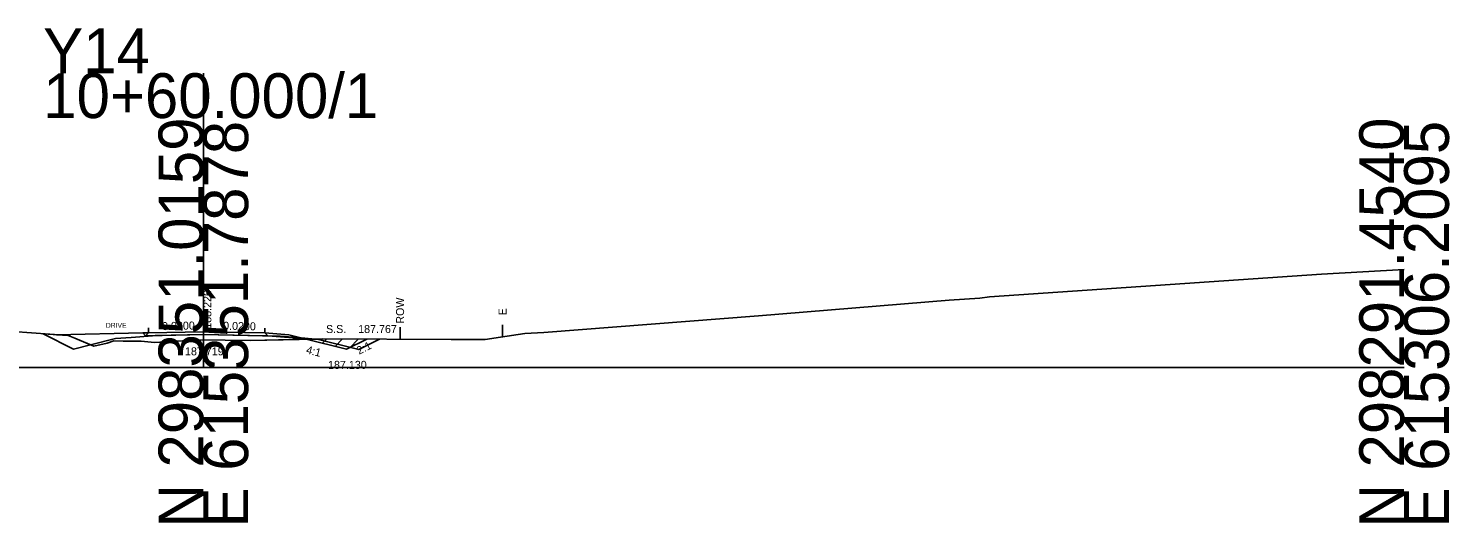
# Model space of a CAD drawing. Extents: x 517327 to 517505, y 114839 to 117370.
# Drawn here: x 517416.4 to 517505.2, y 116338.7 to 116369.5 of the extents above; entities that cross this region are included whole.
import ezdxf

# ---------------------------------------------------------------- set-up
doc = ezdxf.new("R2010")
doc.units = 0
for name, color, linetype in [('Exist XS Ground Line', 7, 'Continuous'), ('Old_Level_60', 7, 'Continuous'), ('Old_Level_63', 7, 'Continuous'), ('Prop XS Dump Level', 7, 'Continuous'), ('Prop XS Earthwork Shape', 7, 'Continuous'), ('Prop XS Elevation Labels', 7, 'Continuous'), ('Prop XS EOT Tick Mark', 7, 'Continuous'), ('Prop XS Exc Vertical Line 1', 7, 'Continuous'), ('Prop XS Exc Vertical Line 2', 7, 'Continuous'), ('Prop XS Finish Grade', 7, 'Continuous'), ('Prop XS Finish Grade Earthwork', 7, 'Continuous'), ('Prop XS Finish Grade Pavement', 7, 'Continuous'), ('Prop XS Hydro Elevations', 7, 'Continuous'), ('Prop XS Label Text', 7, 'Continuous'), ('Prop XS Pvmt Edge Slope', 7, 'Continuous'), ('Prop XS SE Text', 7, 'Continuous'), ('Prop XS Side Slope Text', 7, 'Continuous'), ('Prop XS Subgrade Earthwork', 7, 'Continuous'), ('Prop XS Suitable Common Exc Shape', 7, 'Continuous'), ('Scratch_Level_0', 7, 'Continuous')]:
    doc.layers.add(name, color=color, linetype=linetype)

msp = doc.modelspace()

# ---------------------------------------------------------------- linework, layer by layer
at = {"layer": 'Exist XS Ground Line'}
for p, q in [((517476.474, 116352.763), (517497.196, 116354.197)), ((517497.196, 116354.197), (517502.365, 116354.49)), ((517462.046, 116351.595), (517473.955, 116352.558)), ((517473.955, 116352.558), (517475.855, 116352.699)), ((517475.855, 116352.699), (517476.474, 116352.763)), ((517448.633, 116350.545), (517462.046, 116351.595)), ((517415.494, 116350.598), (517418.926, 116350.355)), ((517418.926, 116350.355), (517419.337, 116350.188)), ((517419.337, 116350.188), (517420.516, 116349.683)), ((517420.516, 116349.683), (517421.365, 116349.878)), ((517421.365, 116349.878), (517421.772, 116350.019)), ((517421.772, 116350.019), (517422.348, 116350.001)), ((517422.348, 116350.001), (517423.492, 116350.003)), ((517423.492, 116350.003), (517424.31, 116349.923)), ((517424.31, 116349.923), (517425.622, 116349.995)), ((517425.622, 116349.995), (517427.362, 116350.084)), ((517427.362, 116350.084), (517428.73, 116350.061)), ((517428.73, 116350.061), (517430.338, 116350.036)), ((517430.338, 116350.036), (517434.785, 116350.148)), ((517434.785, 116350.148), (517442.835, 116350.1)), ((517442.835, 116350.1), (517444.961, 116350.102)), ((517444.961, 116350.102), (517445.929, 116350.255)), ((517445.929, 116350.255), (517447.446, 116350.473)), ((517447.446, 116350.473), (517448.633, 116350.545))]:
    msp.add_line(p, q, dxfattribs=at)
at = {"layer": 'Old_Level_63'}
for p, q in [((517427.365, 116348.365), (517427.365, 116366.739)), ((517352.365, 116348.365), (517427.365, 116348.365)), ((517427.365, 116348.365), (517502.365, 116348.365))]:
    msp.add_line(p, q, dxfattribs=at)
at = {"layer": 'Prop XS Dump Level'}
for p, q in [((517423.941, 116350.523), (517427.365, 116350.591)), ((517427.365, 116350.591), (517431.204, 116350.514))]:
    msp.add_line(p, q, dxfattribs=at)
at = {"layer": 'Prop XS Earthwork Shape'}
for points in [[(517423.758, 116350.339), (517423.941, 116350.343), (517427.365, 116350.411), (517431.204, 116350.334), (517431.387, 116350.331), (517432.704, 116350.225), (517433.698, 116350.146), (517433.788, 116350.123), (517430.338, 116350.036), (517428.73, 116350.061), (517427.362, 116350.084), (517425.622, 116349.995), (517424.31, 116349.923), (517423.492, 116350.003), (517422.348, 116350.001), (517421.772, 116350.019), (517421.365, 116349.878), (517420.516, 116349.683), (517419.337, 116350.188), (517418.926, 116350.355), (517418.186, 116350.407), (517423.581, 116350.515)], [(517436.304, 116349.494), (517437.578, 116350.132), (517434.785, 116350.148), (517433.788, 116350.123)]]:
    msp.add_lwpolyline(points, close=True, dxfattribs=at)
at = {"layer": 'Prop XS EOT Tick Mark'}
for p, q in [((517423.941, 116350.827), (517423.941, 116350.523)), ((517431.204, 116350.514), (517431.204, 116350.819))]:
    msp.add_line(p, q, dxfattribs=at)
at = {"layer": 'Prop XS Exc Vertical Line 1'}
msp.add_line((517446.056, 116351.023), (517446.056, 116350.273), dxfattribs=at)
at = {"layer": 'Prop XS Exc Vertical Line 2'}
msp.add_line((517439.652, 116350.869), (517439.652, 116350.119), dxfattribs=at)
at = {"layer": 'Prop XS Finish Grade'}
for p, q in [((517423.581, 116350.515), (517423.941, 116350.523)), ((517431.204, 116350.514), (517432.704, 116350.394)), ((517432.704, 116350.394), (517433.698, 116350.146))]:
    msp.add_line(p, q, dxfattribs=at)
at = {"layer": 'Prop XS Finish Grade Earthwork'}
for p, q in [((517423.581, 116350.515), (517418.186, 116350.407)), ((517433.698, 116350.146), (517436.304, 116349.494)), ((517436.304, 116349.494), (517437.578, 116350.132))]:
    msp.add_line(p, q, dxfattribs=at)
at = {"layer": 'Prop XS Finish Grade Pavement'}
for p, q in [((517427.365, 116350.591), (517423.941, 116350.523)), ((517431.204, 116350.514), (517427.365, 116350.591))]:
    msp.add_line(p, q, dxfattribs=at)
at = {"layer": 'Prop XS Pvmt Edge Slope'}
for p, q in [((517423.758, 116350.339), (517423.941, 116350.523)), ((517431.204, 116350.514), (517431.387, 116350.331))]:
    msp.add_line(p, q, dxfattribs=at)
at = {"layer": 'Prop XS Subgrade Earthwork'}
for p, q in [((517423.758, 116350.339), (517423.581, 116350.515)), ((517423.758, 116350.339), (517423.941, 116350.343)), ((517427.365, 116350.411), (517423.941, 116350.343)), ((517431.204, 116350.334), (517427.365, 116350.411)), ((517431.204, 116350.334), (517431.387, 116350.331)), ((517431.387, 116350.331), (517432.704, 116350.225)), ((517432.704, 116350.225), (517433.698, 116350.146))]:
    msp.add_line(p, q, dxfattribs=at)
at = {"layer": 'Prop XS Suitable Common Exc Shape'}
for points in [[(517419.337, 116350.188), (517420.309, 116349.772), (517419.265, 116349.511), (517417.355, 116350.466), (517418.926, 116350.355)], [(517433.475, 116350.21), (517434.375, 116350.138), (517430.338, 116350.036), (517428.73, 116350.061), (517427.362, 116350.084), (517425.622, 116349.995), (517424.31, 116349.923), (517423.492, 116350.003), (517422.348, 116350.001), (517421.772, 116350.019), (517421.365, 116349.878), (517420.516, 116349.683), (517420.309, 116349.772), (517421.871, 116350.163), (517422.865, 116350.242), (517424.181, 116350.347), (517424.365, 116350.351), (517427.365, 116350.411), (517431.975, 116350.319), (517432.158, 116350.315)], [(517434.785, 116350.148), (517438.371, 116350.127), (517437.075, 116349.479), (517434.469, 116350.13), (517434.375, 116350.138)]]:
    msp.add_lwpolyline(points, close=True, dxfattribs=at)
at = {"layer": 'Scratch_Level_0'}
for p, q in [((517433.788, 116350.123), (517434.785, 116350.148)), ((517436.304, 116349.494), (517433.788, 116350.123)), ((517434.009, 116350.068), (517434.072, 116350.13)), ((517434.785, 116350.148), (517437.578, 116350.132)), ((517434.801, 116349.87), (517435.078, 116350.146)), ((517435.593, 116349.672), (517436.062, 116350.141)), ((517437.578, 116350.132), (517436.304, 116349.494)), ((517436.508, 116349.596), (517437.046, 116350.135))]:
    msp.add_line(p, q, dxfattribs=at)

# ---------------------------------------------------------------- texts
at = {"layer": 'Old_Level_60'}
msp.add_text('187.719', height=0.5, dxfattribs=at).set_placement((517426.22, 116349.119))
at = {"layer": 'Old_Level_63'}
for s, p in [('Y14', (517417.362, 116366.739)), ('10+60.000/1', (517417.365, 116363.939))]:
    msp.add_text(s, height=2.8, dxfattribs=at).set_placement(p)
for s, p in [('N 298351.0159', (517427.365, 116338.365)), ('E 615351.7878', (517430.165, 116338.365)), ('N 298291.4540', (517502.365, 116338.365)), ('E 615306.2095', (517505.165, 116338.365))]:
    msp.add_text(s, height=2.8, rotation=90, dxfattribs=at).set_placement(p)
at = {"layer": 'Prop XS Dump Level'}
msp.add_text('Case1', height=0.0122, dxfattribs=at).set_placement((517432.704, 116350.382))
at = {"layer": 'Prop XS Elevation Labels'}
msp.add_text(' 188.226', height=0.5, rotation=90, dxfattribs=at).set_placement((517427.865, 116350.591))
at = {"layer": 'Prop XS Exc Vertical Line 1'}
msp.add_text('E', height=0.5, rotation=90, dxfattribs=at).set_placement((517446.306, 116351.616))
at = {"layer": 'Prop XS Exc Vertical Line 2'}
msp.add_text('ROW', height=0.5, rotation=90, dxfattribs=at).set_placement((517439.902, 116351.094))
at = {"layer": 'Prop XS Hydro Elevations'}
msp.add_text('S.S.    187.767', height=0.5, dxfattribs=at).set_placement((517435.028, 116350.512))
at = {"layer": 'Prop XS Label Text'}
msp.add_text('4:1', height=0.5, rotation=345.96376, dxfattribs=at).set_placement((517433.75, 116349.245))
at = {"layer": 'Prop XS SE Text'}
msp.add_text('DRIVE', height=0.3063, dxfattribs=at).set_placement((517421.277, 116350.84))
for rotation, p in [(1.14577, (517424.792, 116350.692)), (358.85424, (517428.597, 116350.719))]:
    msp.add_text('0.0200', height=0.5, rotation=rotation, dxfattribs=at).set_placement(p)
at = {"layer": 'Prop XS Side Slope Text'}
msp.add_text('2:1', height=0.5, rotation=26.56505, dxfattribs=at).set_placement((517437.094, 116349.149))
msp.add_text('187.130', height=0.5, dxfattribs=at).set_placement((517435.153, 116348.274))

doc.saveas('drawing.dxf')
